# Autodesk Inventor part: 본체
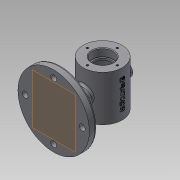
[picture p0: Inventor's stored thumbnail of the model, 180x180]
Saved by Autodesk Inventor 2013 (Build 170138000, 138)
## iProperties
Created: 2018-12
Part Number: 본체
Material: 일반
Document SubType Name: Modeling
Designer: Administrator
Density: 1 g/cm^3
Author: Administrator
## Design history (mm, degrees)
sketch "스케치7"
  geometry: C1 r 30 at (0, 0.503); 1 further point
  constraints: 1 centre point
  dimensions: "d22" = 60 diameter of C1
extrude "돌출5" new body sketch "스케치7" distance "d23" = 70; taper "d24" = 0 deg
sketch "스케치8"
  geometry: C1 r 30 at (0, 0) reference; C2 r 14 at (0, 0); 1 further point
  constraints: 1 centre point, 1 coincident
  dimensions: "d25" = 28 diameter of C2
extrude "돌출6" cut sketch "스케치8" distance "d26" = 70; taper "d27" = 0 deg
sketch "스케치9"
  geometry: C1 r 14 at (0, 0) reference; C2 r 30 at (0, 0) reference; C3 r 16 at (0, 0)
  constraints: 1 centre point, 1 coincident
  dimensions: "d28" = 32 diameter of C3
extrude "돌출7" cut sketch "스케치9" distance "d29" = 12; taper "d30" = 0 deg
sketch "스케치10"
  geometry: C1 r 14 at (0, 0) reference; C2 r 30 at (0, 0) reference; C3 r 16 at (0, 0)
  constraints: 1 centre point, 1 coincident
  dimensions: "d31" = 32 diameter of C3
extrude "돌출8" cut sketch "스케치10" distance "d32" = 12; taper "d33" = 0 deg
sketch "스케치11"
  geometry: L1 (-15.497, 70)-(16.503, 70) reference; L2 (16.503, 0)-(-15.497, 0) reference; L3 (30.503, 0)-(30.503, 70) reference; L4 (0, 35)-(0, 55); L5 (0, 33.432)-(0, 13.432); L6 (14.503, 55)-(25, 55); L7 (14.503, 13.432)-(25, 13.432); L8 (25, 55)-(25, 13.432); L9 (14.503, 58)-(14.503, 12) reference; L10 (14.503, 55)-(14.503, 13.432); L11 (14.503, 58)-(-13.497, 58) reference; L12 (-13.497, 12)-(14.503, 12) reference; L13 (0.503, 70)-(0.503, 53.861); L14 (0.503, 53.861)-(0.503, 0); 1 further point
  constraints: 16 end point, 2 midpoint, 2 perpendicular, 2 point on line, 1 parallel
  dimensions: "d35" = 20 distance of L4.start L4.end; "d36" = 20 distance of L5.start L5.end
revolve "회전1" sketch "스케치11" stored, may be unused: angle "d40" = 90 deg
node "작업 평면1"
sketch "스케치12"
  geometry: L1 (30, 70)-(-30, 70) reference; L2 (-30, 0)-(30, 0) reference; L3 (0, 70)-(0, 35); C1 r 10 at (0, 35); 1 further point
  constraints: 2 end point, 1 centre point, 1 coincident, 1 midpoint, 1 perpendicular
  dimensions: "d42" = 35 distance of L3.start L3.end; "d43" = 20 diameter of C1
extrude "돌출9" join sketch "스케치12" stored distance "d44" = 12; taper "d45" = 0 deg
sketch "스케치13"
  geometry: C1 r 10 at (0, 0) reference; C2 r 5 at (0, 0); 1 further point
  constraints: 1 centre point, 1 coincident
  dimensions: "d46" = 10 diameter of C2
extrude "돌출10" cut sketch "스케치13" stored distance "d47" = 12; taper "d48" = 0 deg
node "작업 평면2"
sketch "스케치14"
  geometry: 1 further point
sketch "스케치15"
  geometry: 1 further point
node "작업 평면3"
sketch "스케치16"
  geometry: L1 (0, -0.503)-(0, -75.503); L2 (0, -75.503)-(0, -66.939); L3 (0, -75.503)-(-55, -75.503); L4 (-55, -75.503)-(-55, -64.503); L5 (-12, -38.003)-(-12, -25.336); L6 (-55, -64.503)-(-26.435, -56.849); L7 (-12, -38.003)-(-12, -52.981); L8 (-26.435, -56.849)-(-12, -52.981); L9 (-12, -25.336)-(0, -27.156); C1 r 30 at (0, 0) reference
  constraints: 18 end point, 2 collinear, 2 perpendicular, 2 point on line, 1 vertical
  dimensions: "d50" = 75 distance of L1.start L1.end; "d51" = 55 distance of L1.end L3.end
revolve "회전2" sketch "스케치16" stored, may be unused: angle "d55" = 90 deg
node "작업 평면4"
sketch "스케치17" dims "d56" = 88
  geometry: C1 r 55 at (0, 0) reference; C2 r 4.5 at (0, 44); C3 r 4.5 at (-44, 0); C4 r 4.5 at (0, -44); C5 r 4.5 at (44, 0); 2 further points
  constraints: 4 centre point, 1 coincident, 1 vertical alignment, 11 other
  dimensions: "d57" = 9 diameter of C2; "d60" = 360 deg dimension on point (0, 0) C2.centre (derived)
extrude "돌출11" cut sketch "스케치17" stored distance "d62" = 23.25; taper "d63" = 0 deg
sketch "스케치18" dims "d64" = 2.5
  geometry: C1 r 55 at (0, 35) reference; 12 further points
  constraints: 24 other
  dimensions: "d68" = 360 deg dimension on C1.centre point (-43.284, 41.963) (derived)
extrude "돌출12" cut sketch "스케치18" distance "d70" = 65; taper "d71" = 0 deg
sketch "스케치19" dims "d72" = 46
  geometry: C1 r 2 at (0, 22.497); C2 r 2 at (-23, -0.503); C3 r 2 at (0, -23.503); C4 r 2 at (23, -0.503); 2 further points
  constraints: 4 centre point, 1 coincident, 1 vertical alignment, 11 other
  dimensions: "d73" = 4 diameter of C1; "d76" = 360 deg dimension on point (0, -0.503) C1.centre (derived)
hole "구멍1" sketch "스케치19" at (0, 22.497), (23, -0.503), (0, -23.503), (-23, -0.503) diameter "d78" = 3.242; stored, may be unused: countersink angle "d82" = 90 deg, drill point angle "d84" = 118 deg; dims "d79" = 8, "d80" = 3.6, "d81" = 2, "d83" = 10
sketch "스케치20"
  geometry: C1 r 23 at (0, -0.503); C2 r 1.621 at (0, 22.497) reference; C3 r 1.621 at (-23, -0.503) reference; C4 r 1.621 at (0, -23.503) reference; C5 r 1.621 at (23, -0.503) reference; 1 further point
  constraints: 1 centre point, 1 coincident
  dimensions: "d85" = 46 diameter of C1
hole "구멍2" sketch "스케치20" at (0, 22.497), (-23, -0.503), (0, -23.503), (23, -0.503) diameter "d86" = 3.242; stored, may be unused: countersink angle "d90" = 90 deg, drill point angle "d92" = 118 deg; dims "d87" = 8, "d88" = 3.6, "d89" = 2, "d91" = 10
fillet "모깎기1" dims "d93" = 0.3, "d94" = 0.3
chamfer "모따기1" distance "d95" = 1; stored, may be unused: second distance "d96" = 2, angle "d97" = 45 deg
fillet "모깎기2" dims "d98" = 3
fillet "모깎기3" dims "d99" = 3
fillet "모깎기4" dims "d100" = 3
sketch "스케치21"
  geometry: 1 further point
node "작업 평면5"
sketch "스케치22"
  geometry: L1 (30, 70)-(-30, 70) reference; L2 (30, 0)-(30, 70) reference; 2 further points
  constraints: 1 other
  dimensions: "d101" = 35 distance from line of point (0, 35) L1; "d102" = 30 distance from line of point (0, 35) L2
feature "엠보싱1" sketch "스케치22" dims "d31" = 32, "d103" = 1, "d104" = 0
node "솔리드2"
node "투영된 루프3"
other parameters: "d41" = 37, "d49" = -75
